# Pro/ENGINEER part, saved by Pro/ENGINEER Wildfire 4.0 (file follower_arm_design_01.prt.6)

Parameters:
  METRIC = "NO"

Other parameters: PITCH, DRILL_DIAMETER, THREAD_DIAMETER, THREADS_PER_INCH, THREAD_DEPTH, THREAD_LENGTH, DRILL_POINT_ANGLE, DRILL_DEPTH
